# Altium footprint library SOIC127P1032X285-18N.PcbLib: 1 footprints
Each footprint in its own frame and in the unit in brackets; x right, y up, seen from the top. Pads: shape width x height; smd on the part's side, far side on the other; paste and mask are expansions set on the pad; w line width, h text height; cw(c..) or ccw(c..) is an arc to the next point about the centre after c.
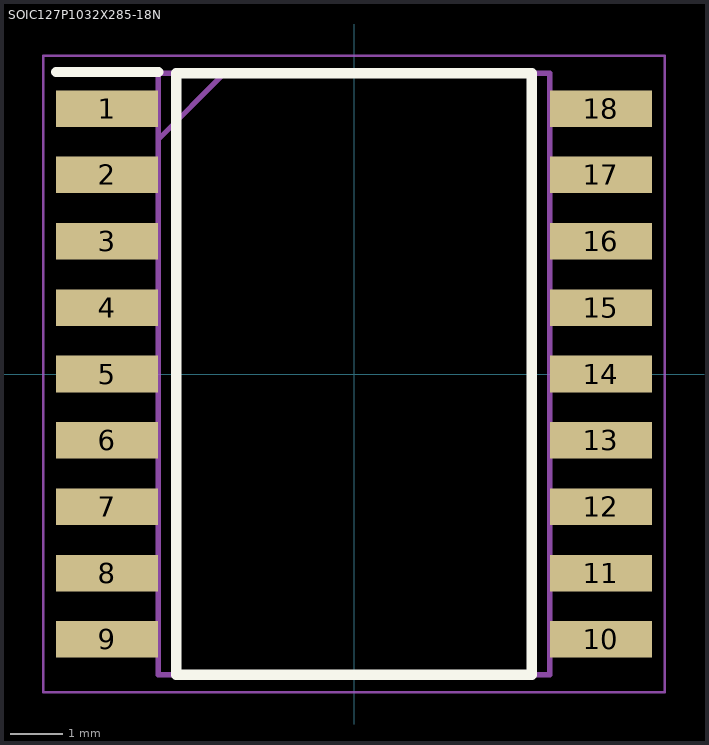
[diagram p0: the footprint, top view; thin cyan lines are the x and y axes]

## SOIC127P1032X285-18N [mm]
pads (18):
  rect 1.95x0.7 smd: 1(-4.725,5.08) 2(-4.725,3.81) 3(-4.725,2.54) 4(-4.725,1.27) 5(-4.725,0) 6(-4.725,-1.27) 7(-4.725,-2.54) 8(-4.725,-3.81) 9(-4.725,-5.08) 10(4.725,-5.08) 11(4.725,-3.81) 12(4.725,-2.54) 13(4.725,-1.27) 14(4.725,0) 15(4.725,1.27) 16(4.725,2.54) 17(4.725,3.81) 18(4.725,5.08)
Top Overlay:
  lines w0.2: -5.7,5.78 -3.75,5.78 ; -3.4,-5.758 3.4,-5.758 3.4,5.758 -3.4,5.758 -3.4,-5.758
Mechanical 15:
  lines w0.1: -3.748,4.488 -2.478,5.758 ; -3.748,-5.758 3.748,-5.758 3.748,5.758 -3.748,5.758 -3.748,-5.758
Mechanical 20:
  lines w0.05: -5.95,-6.09 5.95,-6.09 5.95,6.09 -5.95,6.09 -5.95,-6.09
